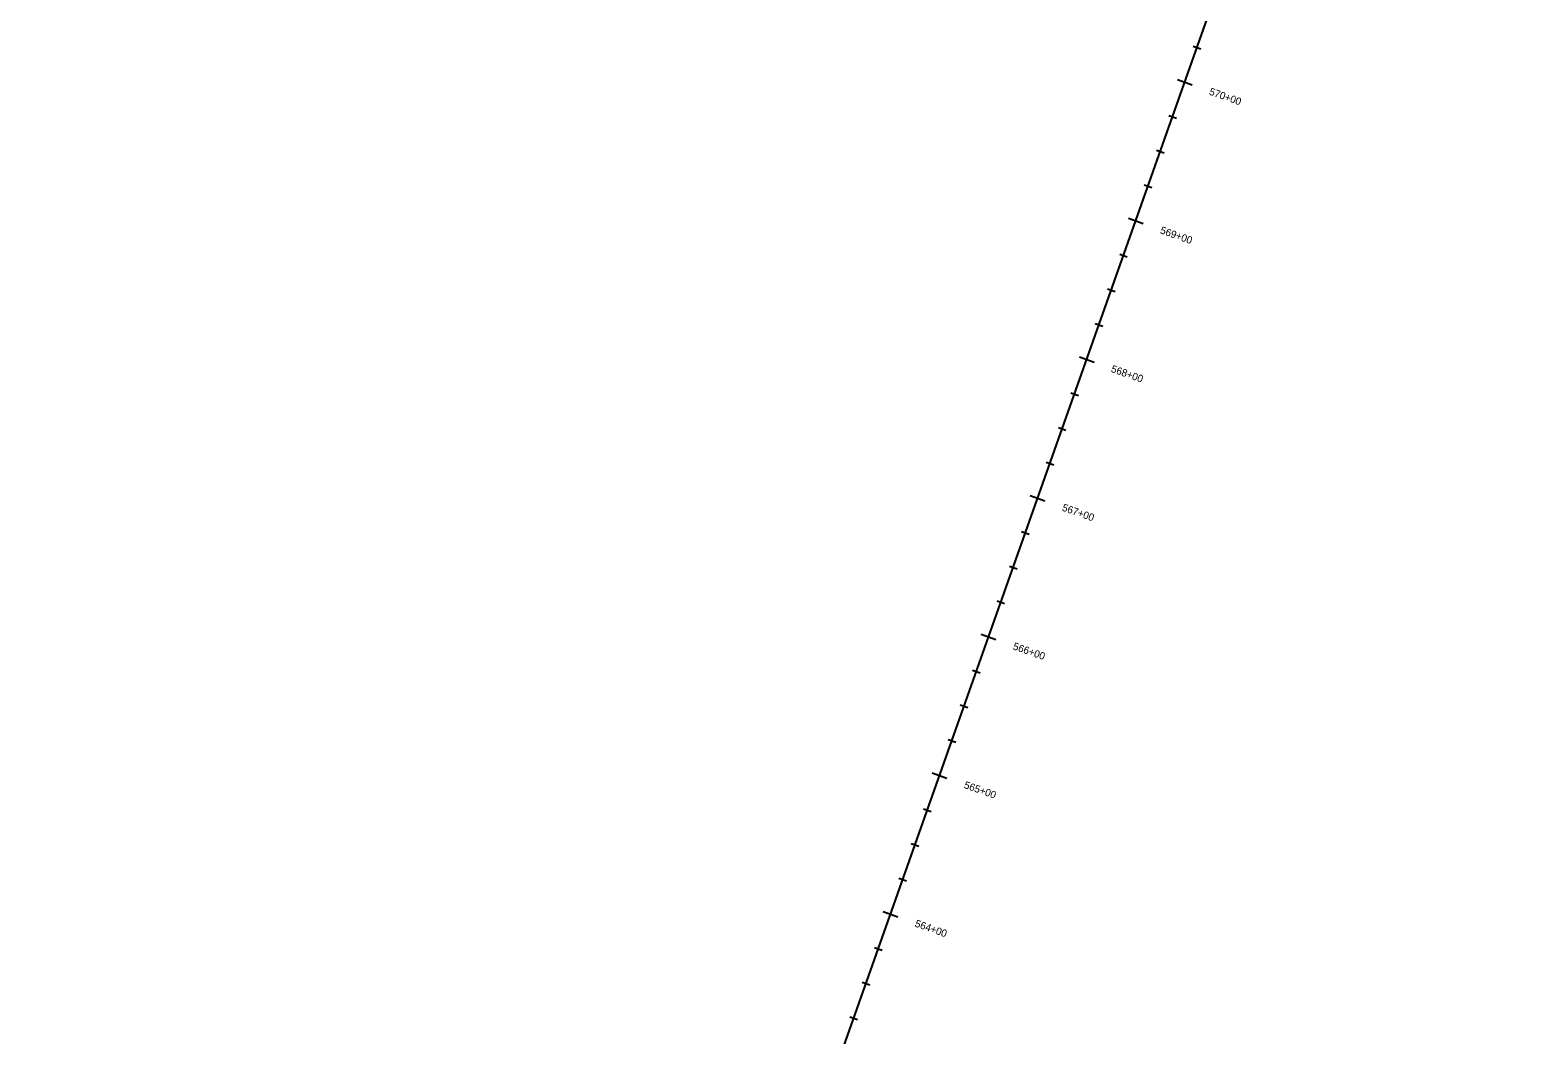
# Model space of a CAD drawing. Extents: x 2300830 to 2307917, y 756066 to 766359.
# Drawn here: x 2304442 to 2305467, y 764996 to 765680 of the extents above; entities that cross this region are included whole.
import ezdxf

# ---------------------------------------------------------------- set-up
doc = ezdxf.new("R2010")
doc.units = 0
for name, color, linetype in [('Default', 7, 'Continuous'), ('Draft_Station Labels Major', 7, 'Continuous'), ('Draft_Station Ticks Major', 7, 'Continuous'), ('Draft_Station Ticks Minor', 7, 'Continuous'), ('Geom_Baseline', 7, 'Continuous')]:
    doc.layers.add(name, color=color, linetype=linetype)

msp = doc.modelspace()

# ---------------------------------------------------------------- linework, layer by layer
at = {"layer": 'Default'}
msp.add_line((2304441.8, 763425), (2305466.9, 766322.6), dxfattribs=at)
at = {"layer": 'Draft_Station Ticks Major'}
for p, q in [((2305221.9, 765646), (2305231.9, 765642.4)), ((2305188.5, 765551.7), (2305198.5, 765548.1)), ((2305155.2, 765457.4), (2305165.2, 765453.9)), ((2305121.8, 765363.1), (2305131.8, 765359.6)), ((2305088.5, 765268.9), (2305098.5, 765265.3)), ((2305055.1, 765174.6), (2305065.1, 765171)), ((2305021.8, 765080.3), (2305031.8, 765076.8))]:
    msp.add_line(p, q, dxfattribs=at)
at = {"layer": 'Draft_Station Ticks Minor'}
for p, q in [((2305232.6, 765668.7), (2305237.9, 765666.8)), ((2305216, 765621.5), (2305221.2, 765619.7)), ((2305207.6, 765598), (2305212.8, 765596.1)), ((2305199.3, 765574.4), (2305204.5, 765572.5)), ((2305182.6, 765527.3), (2305187.8, 765525.4)), ((2305174.3, 765503.7), (2305179.5, 765501.8)), ((2305165.9, 765480.1), (2305171.1, 765478.3)), ((2305149.3, 765433), (2305154.5, 765431.1)), ((2305140.9, 765409.4), (2305146.1, 765407.6)), ((2305132.6, 765385.8), (2305137.8, 765384)), ((2305115.9, 765338.7), (2305121.1, 765336.9)), ((2305107.6, 765315.1), (2305112.8, 765313.3)), ((2305099.2, 765291.6), (2305104.4, 765289.7)), ((2305082.6, 765244.4), (2305087.8, 765242.6)), ((2305074.2, 765220.9), (2305079.4, 765219)), ((2305065.9, 765197.3), (2305071.1, 765195.5)), ((2305049.2, 765150.2), (2305054.4, 765148.3)), ((2305040.9, 765126.6), (2305046.1, 765124.7)), ((2305032.5, 765103), (2305037.7, 765101.2)), ((2305015.8, 765055.9), (2305021.1, 765054)), ((2305007.5, 765032.3), (2305012.7, 765030.5)), ((2304999.2, 765008.7), (2305004.4, 765006.9))]:
    msp.add_line(p, q, dxfattribs=at)
at = {"layer": 'Geom_Baseline'}
msp.add_line((2304441.8, 763425), (2305466.9, 766322.6), dxfattribs=at)

# ---------------------------------------------------------------- texts
at = {"layer": 'Draft_Station Labels Major'}
for s, p in [('570+00', (2305243, 765635.8)), ('569+00', (2305209.7, 765541.5)), ('568+00', (2305176.3, 765447.3)), ('567+00', (2305143, 765353)), ('566+00', (2305109.6, 765258.7)), ('565+00', (2305076.3, 765164.4)), ('564+00', (2305042.9, 765070.2))]:
    msp.add_text(s, height=5, rotation=340.5164, dxfattribs=at).set_placement(p)

doc.saveas('drawing.dxf')
